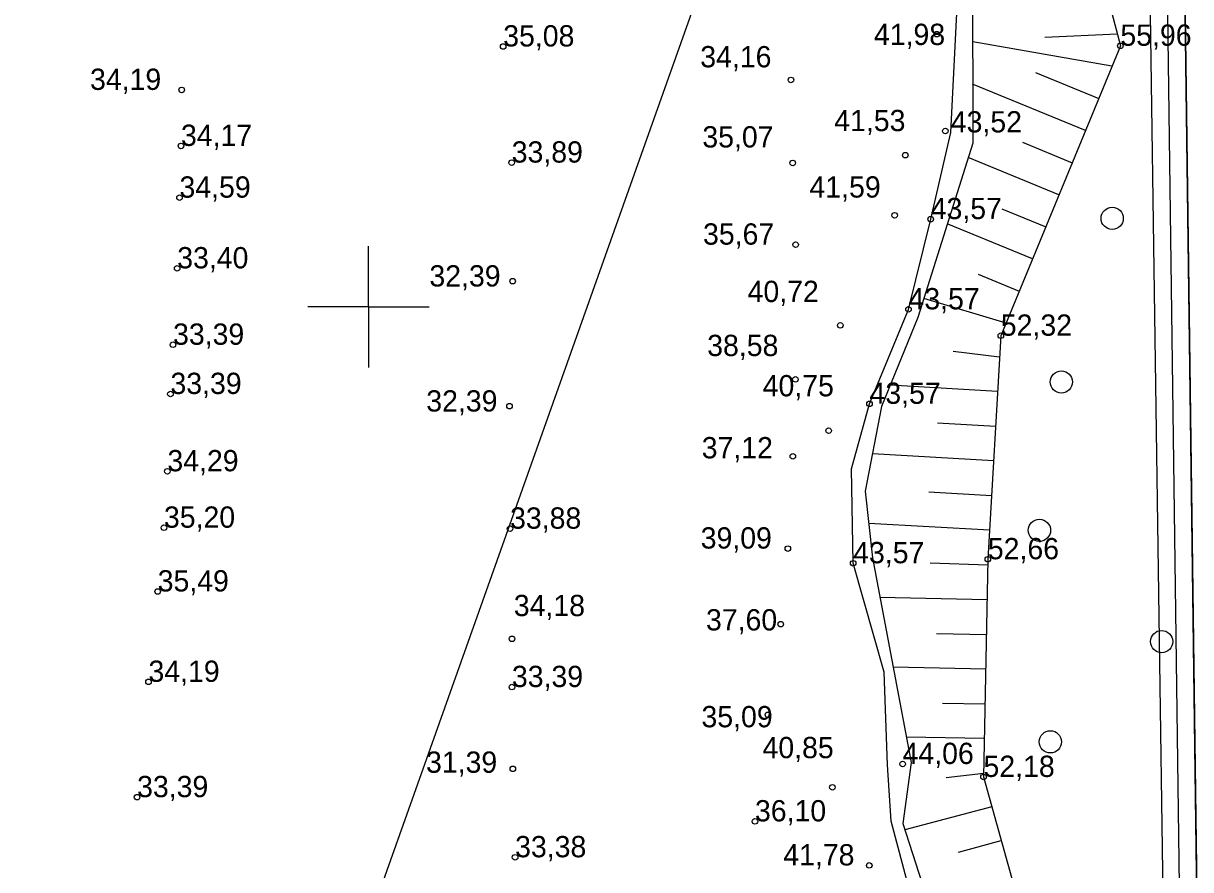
# Model space of a CAD drawing. Extents: x 700746 to 706058, y 6570320 to 6580460.
# Drawn here: x 703160.3 to 703294.7, y 6575835.2 to 6575932.6 of the extents above; entities that cross this region are included whole.
import ezdxf

# ---------------------------------------------------------------- set-up
doc = ezdxf.new("R2010")
doc.units = 0
for name, color, linetype in [('HALJASTUS', 7, 'Continuous'), ('illumineerimisjooned', 7, 'Continuous'), ('kataster', 7, 'Continuous'), ('KORGUS-EH2000', 7, 'Continuous'), ('Lõige', 7, 'Continuous'), ('Plokid', 7, 'Continuous'), ('RELJEEF', 7, 'Continuous'), ('Tmaad_maeeraldised_kehtivad', 7, 'Continuous'), ('VEEKOGU', 7, 'Continuous'), ('VORK', 7, 'Continuous'), ('VWX2_MV_PLOKK', 7, 'Continuous')]:
    doc.layers.add(name, color=color, linetype=linetype)

msp = doc.modelspace()

# ---------------------------------------------------------------- linework, layer by layer
at = {"layer": 'HALJASTUS'}
for centre in [(703285.64, 6575910.18), (703279.79, 6575891.35), (703277.26, 6575874.27), (703291.33, 6575861.45), (703278.52, 6575849.9)]:
    msp.add_circle(centre, 1.28, dxfattribs=at)
at = {"layer": 'illumineerimisjooned'}
msp.add_lwpolyline([(703275.45, 6577071.68), (703358.03, 6576531.93), (703309.57, 6576228.79), (703291.69, 6575965.8), (703292.02, 6575933.77), (703296.8, 6575575.06), (702854, 6575511.22), (702839.23, 6575620.77), (702850.34, 6575977.31), (702784.78, 6576064.06), (702784.62, 6576095.83), (702844.43, 6576209.85), (702855.46, 6576267.3), (702846.53, 6576489.41), (702878.89, 6576547.09), (702976.89, 6576643.26), (702915.33, 6577059.56)], dxfattribs=at)
at = {"layer": 'kataster'}
msp.add_lwpolyline([(702852.27, 6575508.89), (702837.26, 6575620.73), (702848.38, 6575976.59), (702782.85, 6576063.35), (702782.57, 6576096.37), (702842.53, 6576210.56), (702853.4, 6576267.5), (702844.46, 6576489.93), (702877.29, 6576548.25), (702974.72, 6576643.9), (702913.57, 6577058.07), (702784.04, 6577102.84), (702746.48, 6577248.7), (702719.69, 6577297.36), (702713.81, 6577334.91), (703089.87, 6577211.79), (703231.53, 6577106.55), (703277.36, 6577072.83), (703360.09, 6576531.99), (703311.6, 6576228.52), (703293.62, 6575965.66), (703298.84, 6575573.29)], close=True, dxfattribs=at)
at = {"layer": 'KORGUS-EH2000'}
for centre in [(703265.45, 6575931.4), (703215.51, 6575929.98), (703286.58, 6575930.06), (703178.49, 6575924.98), (703248.64, 6575926.13), (703266.43, 6575920.25), (703178.4, 6575918.53), (703261.81, 6575917.47), (703216.49, 6575916.61), (703248.85, 6575916.57), (703178.23, 6575912.57), (703260.58, 6575910.54), (703264.74, 6575910.1), (703249.18, 6575907.16), (703177.97, 6575904.43), (703216.6, 6575902.95), (703262.18, 6575899.71), (703254.33, 6575897.86), (703177.49, 6575895.63), (703272.81, 6575896.67), (703249.16, 6575891.64), (703177.19, 6575889.96), (703257.69, 6575888.83), (703216.24, 6575888.56), (703252.98, 6575885.74), (703248.86, 6575882.78), (703176.84, 6575881.06), (703176.44, 6575874.56), (703216.3, 6575874.45), (703248.29, 6575872.16), (703255.81, 6575870.47), (703271.32, 6575870.93), (703175.72, 6575867.22), (703247.47, 6575863.45), (703216.52, 6575861.77), (703174.66, 6575856.81), (703216.51, 6575856.21), (703245.99, 6575853.01), (703261.5, 6575847.35), (703216.62, 6575846.79), (703270.82, 6575845.86), (703253.42, 6575844.67), (703173.35, 6575843.53), (703244.5, 6575840.74), (703216.88, 6575836.61), (703257.66, 6575835.67)]:
    msp.add_circle(centre, 0.32, dxfattribs=at)
at = {"layer": 'Lõige'}
msp.add_lwpolyline([(703258.61, 6575994.21), (703143.06, 6575668.99)], dxfattribs=at)
at = {"layer": 'Plokid'}
msp.add_lwpolyline([(703290.64, 6576959.22), (703356.01, 6576531.94), (703307.59, 6576229.01), (703289.69, 6575965.85), (703290.02, 6575933.75), (703291.51, 6575829.64), (703294.32, 6575609.52), (703294.77, 6575576.79), (703154.76, 6575556.6), (703019.06, 6575536.97), (703053.36, 6575698.14), (703145.59, 6575981.92), (703123.04, 6576234.88), (703120.61, 6576749.6), (703011.59, 6576989.47), (702968.34, 6577084.63), (702917.3, 6577059.88)], dxfattribs=at)
at = {"layer": 'RELJEEF'}
for p, q in [((703277.89, 6575931.04), (703286.21, 6575931.45)), ((703285.61, 6575927.7), (703269.59, 6575930.52)), ((703276.82, 6575926.99), (703284.08, 6575924)), ((703282.56, 6575920.3), (703269.57, 6575925.66)), ((703275.3, 6575918.96), (703281.03, 6575916.6)), ((703279.51, 6575912.9), (703269.06, 6575917.21)), ((703272.92, 6575911.29), (703277.98, 6575909.21)), ((703276.46, 6575905.51), (703266.65, 6575909.55)), ((703270.19, 6575903.77), (703274.93, 6575901.81)), ((703273.41, 6575898.11), (703263.93, 6575900.94)), ((703267.31, 6575894.9), (703272.67, 6575894.23)), ((703272.44, 6575890.24), (703260.08, 6575890.96)), ((703265.51, 6575886.64), (703272.21, 6575886.25)), ((703271.97, 6575882.25), (703258.04, 6575883.07)), ((703264.51, 6575878.68), (703271.74, 6575878.26)), ((703271.51, 6575874.27), (703257.6, 6575875.03)), ((703264.69, 6575870.51), (703271.3, 6575870.27)), ((703271.23, 6575866.27), (703258.88, 6575866.52)), ((703265.4, 6575862.39), (703271.15, 6575862.28)), ((703271.07, 6575858.28), (703260.41, 6575858.49)), ((703266.08, 6575854.37), (703270.99, 6575854.28)), ((703270.91, 6575850.28), (703261.94, 6575850.45)), ((703266.51, 6575845.8), (703270.83, 6575846.28)), ((703271.79, 6575842.41), (703261.76, 6575839.78)), ((703267.94, 6575837.19), (703272.86, 6575838.56))]:
    msp.add_line(p, q, dxfattribs=at)
for points in [[(703247.69, 6576093.18), (703243.06, 6576086.17), (703252.95, 6576077.09), (703261.8, 6576070.11), (703268.77, 6576058.43), (703271.33, 6576046.5), (703267.89, 6576026.92), (703271.05, 6575998.57), (703264.14, 6575971.19), (703269.54, 6575938.43), (703269.58, 6575918.85), (703263.25, 6575898.76), (703259.09, 6575888.52), (703257.21, 6575878.77), (703258.02, 6575871.08), (703262.5, 6575847.54), (703261.53, 6575840.5), (703265.2, 6575829.05), (703263.8, 6575813.78), (703261.82, 6575803.24), (703263.01, 6575785.91), (703261.77, 6575747.86), (703259.12, 6575693.43)], [(703265.55, 6576092.54), (703268.13, 6576079.38), (703288.06, 6576052.31), (703288.2, 6576001.12), (703276.32, 6575968.87), (703286.58, 6575930.06), (703272.81, 6575896.67), (703271.32, 6575870.93), (703270.82, 6575845.86), (703279.4, 6575815.02), (703271.16, 6575743.04), (703271.27, 6575694.26)]]:
    msp.add_lwpolyline(points, dxfattribs=at)
at = {"layer": 'Tmaad_maeeraldised_kehtivad'}
msp.add_lwpolyline([(703277.3, 6577072.8), (703360.06, 6576531.93), (703311.56, 6576228.56), (703293.69, 6575965.74), (703294.02, 6575933.8), (703298.82, 6575573.33), (702852.29, 6575508.95), (702837.23, 6575620.66), (702848.32, 6575976.66), (702782.78, 6576063.39), (702782.61, 6576096.32), (702842.53, 6576210.52), (702853.45, 6576267.45), (702844.51, 6576489.89), (702877.28, 6576548.31), (702974.76, 6576643.97), (702913.53, 6577058.07)], dxfattribs=at)
at = {"layer": 'VEEKOGU'}
msp.add_lwpolyline([(703263.6, 6575827.89), (703260.17, 6575840.76), (703259.75, 6575847.24), (703259.38, 6575857.91), (703255.81, 6575870.47), (703255.62, 6575881.34), (703257.69, 6575888.83), (703262.18, 6575899.71), (703264.74, 6575910.1), (703267.05, 6575920.08), (703268.02, 6575939.19), (703261.6, 6575964.73), (703263.57, 6575980.82), (703268.73, 6575998.15), (703265.48, 6576026.74), (703269.71, 6576045.08), (703267.18, 6576057.85), (703260.94, 6576069.86), (703251.55, 6576076.17), (703242.36, 6576086.56), (703246.24, 6576093.9)], dxfattribs=at)
msp.add_lwpolyline([(703263.6, 6575827.89), (703260.17, 6575840.76), (703259.75, 6575847.24), (703259.38, 6575857.91), (703255.81, 6575870.47), (703255.62, 6575881.34), (703257.69, 6575888.83), (703262.18, 6575899.71), (703264.74, 6575910.1), (703267.05, 6575920.08), (703268.02, 6575939.19), (703261.6, 6575964.73), (703263.57, 6575980.82), (703268.73, 6575998.15), (703265.48, 6576026.74), (703269.71, 6576045.08), (703267.18, 6576057.85), (703260.94, 6576069.86), (703251.55, 6576076.17), (703242.36, 6576086.56), (703246.24, 6576093.9)], dxfattribs=at)
at = {"layer": 'VORK'}
for q in [(703200, 6575907), (703200, 6575907), (703200, 6575907), (703200, 6575907), (703193, 6575900), (703193, 6575900), (703207, 6575900), (703200, 6575893), (703207, 6575900), (703200, 6575893)]:
    msp.add_line((703200, 6575900), q, dxfattribs=at)
at = {"layer": 'VWX2_MV_PLOKK'}
for points in [[(703044.07, 6577449.05), (703125.37, 6577441.7), (703167.08, 6577172.26), (703170.22, 6577152.1), (703231.53, 6577106.55), (703277.36, 6577072.83), (703360.09, 6576531.99), (703311.6, 6576228.52), (703293.62, 6575965.66), (703294.04, 6575933.77), (703295.43, 6575829.7), (703298.36, 6575609.6), (703298.84, 6575573.29), (703155.29, 6575552.59), (703145.59, 6575981.92), (703123.04, 6576234.88), (703120.61, 6576749.6), (703011.59, 6576989.47), (703015.74, 6577110.88), (702996.73, 6577210.32)], [(703443.86, 6575689.39), (703467.13, 6575602.53), (703308.24, 6575608.65), (703295.44, 6575828.99), (703294.04, 6575933.77), (703311.73, 6576015.89), (703324.97, 6576203.33), (703382.07, 6576503.63), (703406.94, 6576414.24), (703421.77, 6576214.18)]]:
    msp.add_lwpolyline(points, close=True, dxfattribs=at)
msp.add_lwpolyline([(703187.67, 6576999.67), (703190.39, 6576656.32), (703340.88, 6576657.54), (703360.09, 6576531.99), (703311.6, 6576228.52), (703293.62, 6575965.66), (703294.04, 6575933.77), (703295.43, 6575829.7), (703298.36, 6575609.6), (703298.84, 6575573.29), (703155.29, 6575552.59), (703018.17, 6575532.81), (703053.36, 6575698.14), (703145.59, 6575981.92), (703123.04, 6576234.88), (703120.61, 6576749.6), (703011.59, 6576989.47)], dxfattribs=at)
msp.add_lwpolyline([(703187.67, 6576999.67), (703190.39, 6576656.32), (703340.88, 6576657.54), (703360.09, 6576531.99), (703311.6, 6576228.52), (703293.62, 6575965.66), (703294.04, 6575933.77), (703295.43, 6575829.7), (703298.36, 6575609.6), (703298.84, 6575573.29), (703155.29, 6575552.59), (703018.17, 6575532.81), (703053.36, 6575698.14), (703145.59, 6575981.92), (703123.04, 6576234.88), (703120.61, 6576749.6), (703011.59, 6576989.47)], dxfattribs=at)

# ---------------------------------------------------------------- texts
at = {"layer": 'KORGUS-EH2000'}
for s, p in [('35,08 ', (703215.51, 6575929.98)), ('41,98 ', (703258.2, 6575930.15)), ('55,96 ', (703286.58, 6575930.06)), ('34,16 ', (703238.2, 6575927.58)), ('34,19 ', (703167.93, 6575924.98)), ('41,53 ', (703253.63, 6575920.23)), ('43,52 ', (703267.05, 6575920.08)), ('34,17 ', (703178.4, 6575918.53)), ('35,07 ', (703238.44, 6575918.35)), ('33,89 ', (703216.49, 6575916.61)), ('34,59 ', (703178.23, 6575912.57)), ('41,59 ', (703250.78, 6575912.58)), ('43,57 ', (703264.74, 6575910.1)), ('35,67 ', (703238.52, 6575907.16)), ('33,40 ', (703177.97, 6575904.43)), ('32,39 ', (703207.01, 6575902.34)), ('40,72 ', (703243.65, 6575900.55)), ('43,57 ', (703262.18, 6575899.71)), ('52,32 ', (703272.81, 6575896.67)), ('33,39 ', (703177.49, 6575895.63)), ('38,58 ', (703239, 6575894.33)), ('33,39 ', (703177.19, 6575889.96)), ('40,75 ', (703245.39, 6575889.69)), ('32,39 ', (703206.65, 6575887.94)), ('43,57 ', (703257.69, 6575888.83)), ('37,12 ', (703238.37, 6575882.55)), ('34,29 ', (703176.84, 6575881.06)), ('35,20 ', (703176.44, 6575874.56)), ('33,88 ', (703216.3, 6575874.45)), ('39,09 ', (703238.25, 6575872.16)), ('43,57 ', (703255.81, 6575870.47)), ('52,66 ', (703271.32, 6575870.93)), ('35,49 ', (703175.72, 6575867.22)), ('34,18 ', (703216.73, 6575864.38)), ('37,60 ', (703238.86, 6575862.73)), ('34,19 ', (703174.66, 6575856.81)), ('33,39 ', (703216.51, 6575856.21)), ('35,09 ', (703238.34, 6575851.58)), ('40,85 ', (703245.37, 6575848.02)), ('31,39 ', (703206.62, 6575846.34)), ('44,06 ', (703261.5, 6575847.35)), ('52,18 ', (703270.82, 6575845.86)), ('33,39 ', (703173.35, 6575843.53)), ('36,10 ', (703244.5, 6575840.74)), ('33,38 ', (703216.88, 6575836.61)), ('41,78 ', (703247.76, 6575835.67))]:
    msp.add_text(s, height=2.45, dxfattribs=at).set_placement(p)

doc.saveas('drawing.dxf')
